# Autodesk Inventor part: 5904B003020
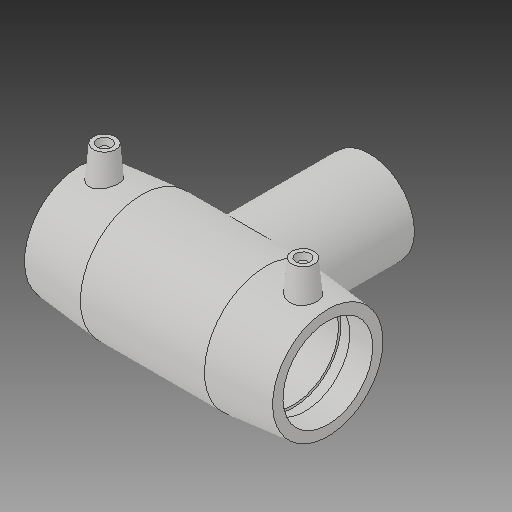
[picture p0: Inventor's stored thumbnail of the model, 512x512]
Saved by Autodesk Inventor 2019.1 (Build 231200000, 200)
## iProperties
Created: 2017-06
Part Number: 5904B003020
Material: Generic
Description: PLASSON TEE 2''IPS
Document SubType Name: Modeling
Designer: KIM
Mass: 17327.5 g
Surface Area: 12195.1 cm^2
Volume: 17327.5 cm^3
Density: 1 g/cm^3
Appearance: Default
Author: KIM
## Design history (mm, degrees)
derived "5904B.ipt"
feature "Solid1::5904B.ipt"
tag "TaggingFeature1"
body "Solid1"
other parameters: "d0" = 166.116, "d1" = 60.1, "d2" = 82.042, "d3" = 57.404, "d4" = 41.529, "d5" = 73.8378, "d6" = 57.095, "d7" = 60.1, "d8" = 168 deg, "d10" = 22.9616, "d11" = 7.65387, "d13" = 166.116, "d14" = 17.6296, "d17" = 54.09, "d18" = 60.1, "d19" = 3.52592, "d20" = 168 deg, "d22" = 76.29906, "d23" = 82.042, "d24" = 74.01009, "d25" = 135 deg, "d26" = 116.2812, "d27" = 135 deg, "d29" = 58.42, "d30" = 15, "d31" = 66.4464, "d34" = 5 deg, "d35" = 15, "d39" = 5 deg, "d40" = 9.6, "d41" = 4.8, "d42" = 6, "d43" = 0, "d45" = 4, "d46" = 14, "d47" = 0, "d48" = -110.998, "d49" = 60.1, "d51" = 0, "d52" = 48.08, "d54" = 0, "d55" = 73.8378, "d56" = 82.042, "d57" = 58.1406, "d58" = 135 deg, "d59" = 57.404, "d60" = 57.404, "d61" = 135 deg, "d62" = 110.998, "d72" = 75.58278, "d73" = 37.79139, "d74" = -110.998, "d75" = 63.105, "d77" = 0, "d78" = 48.08, "d80" = 0, "d81" = 60.1, "d82" = 69.977, "d83" = 0, "d84" = 3, "d85" = 0, "d86" = 3, "d87" = 0, "d88" = 16.64716, "d89" = 4.16179, "d90" = 16.64716, "d_" = 60.1, "L_" = 166.116, "L_1" = 57.404, "D_" = 82.042, "A_" = 58.42, "d_2" = 12, "H_" = 110.998
